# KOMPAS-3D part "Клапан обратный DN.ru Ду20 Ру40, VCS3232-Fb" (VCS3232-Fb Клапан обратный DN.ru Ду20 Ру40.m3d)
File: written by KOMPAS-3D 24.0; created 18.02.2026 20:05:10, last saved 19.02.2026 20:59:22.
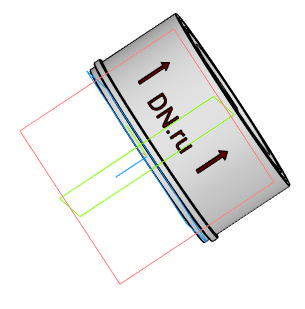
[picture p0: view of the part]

Document properties: Автор: R2D2; Полное имя файла: D:\Работа\Клапаны обратные\VCS3232-Fb Клапан обратный DN.ru Ду15-100\DN20\VCS3232-Fb Клапан обратный DN.ru Ду20 Ру40.m3d

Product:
- Body: Тело 1  | qty 1
    Масса: 0.149728
- Body: Тело 2  | qty 1
    Масса: 0.03963
- Part/product: Клапан обратный DN.ru Ду20 Ру40  | designation VCS3232-Fb
    Масса: 0.28
    Раздел спецификации: Прочие изделия
    Примечание: D100-03706
    additional columns: 1; D100-03706

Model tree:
1. Операция без истории:8
2. Операция без истории:9

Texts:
  Точка начала. Х
  Точка начала. Y
  Точка начала. Z
  VCS3232-Fb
